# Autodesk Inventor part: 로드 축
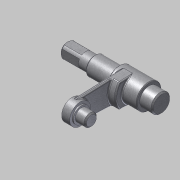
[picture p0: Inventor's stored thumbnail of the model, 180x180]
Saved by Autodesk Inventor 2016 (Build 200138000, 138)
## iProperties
Created: 2015-10
Part Number: 로드 축
Document SubType Name: Modeling
Designer: mdu
Density: 7.86 g/cm^3
Material: 강철, 연강
Mass: 151.797 g
Surface Area: 62.904 cm^2
Volume: 19.3125 cm^3
Appearance: 금속-강(스테인리스, 브러시됨)
Author: mdu
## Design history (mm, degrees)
sketch "스케치1"
  geometry: L1 (-3.325, 13.5)-(-3.325, -13.5) reference; L2 (48.675, -15.7)-(48.675, 15.7) reference; L3 (48.675, 0)-(-26.325, 0); L4 (39.675, -18.06)-(39.675, 18.06) reference; L5 (15.675, 18.855)-(15.675, -18.855) reference; L6 (6.675, 15.7)-(6.675, -15.7) reference; L7 (3.675, -10)-(3.675, 10) reference; L8 (49.675, 7.5)-(39.675, 7.5); L9 (39.675, 7.5)-(39.675, 10); L10 (39.675, 10)-(15.675, 10); L11 (15.675, 10)-(15.675, 7.5); L12 (15.675, 7.5)-(-4.325, 7.5); L13 (-4.325, 7.5)-(-4.325, 6); L14 (-4.325, 6)-(-26.325, 6); L15 (-26.325, 6)-(-26.325, 0); L16 (48.675, 0)-(49.675, 0); L17 (49.675, 0)-(49.675, 7.5); 1 further point
  constraints: 22 end point, 7 perpendicular, 4 point on line, 2 parallel, 1 collinear, 1 midpoint
  dimensions: "d0" = 15 diameter of L8 L3; "d1" = 20 diameter of L10 L3; "d2" = 12 diameter of L14 L3; "d3" = 20 distance of L11.end L12.end; "d4" = 1 distance between parallel lines of L17 L2; "d5" = 75 distance of L3.start L3.end
revolve "회전1" sketch "스케치1" stored, may be unused: angle "d6" = 90 deg
chamfer "모따기1" distance "d7" = 1; stored, may be unused: second distance "d8" = 2, angle "d9" = 45 deg
node "작업 평면1"
sketch "스케치2"
  geometry: 1 further point
sketch "스케치3"
  geometry: L1 (9.993, -0.375)-(8.494, -40.319); L2 (-8.494, -40.319)-(-9.993, -0.375); C1 r 10 at (0, 0) reference; A1 r 8.5 centre (0, -40) between (8.494, -40.319) and (-8.494, -40.319); A2 r 10 centre (0, 0) between (-9.993, -0.375) and (9.993, -0.375) reference; 1 further point
  constraints: 4 end point, 4 point on circle, 4 tangent, 1 centre point, 1 vertical alignment
  dimensions: "d12" = 17 diameter of A1; "d22" = 40 distance of A1.centre A2.centre
  node "투영된 루프1"
extrude "돌출1" join sketch "스케치3" distance "d13" = 6.5; taper "d14" = 0 deg
node "작업 평면3"
  node "작업 평면2"
extrude "돌출2" join sketch "스케치3" stored distance "d17" = 6; taper "d18" = 0 deg
sketch "스케치7"
  geometry: L1 (-9.993, -0.375)-(-8.494, -40.319) reference; L2 (8.494, -40.319)-(9.993, -0.375) reference; A1 r 10 centre (0, 0) between (-9.993, -0.375) and (9.993, -0.375) reference; A2 r 15 centre (0, 0) between (-9.574, -11.547) and (9.574, -11.547); 1 further point
  constraints: 2 point on circle, 2 point on line, 1 centre point, 1 coincident
  dimensions: "d32" = 30 diameter of A2
extrude "돌출6" join sketch "스케치7" distance "d33" = 6; taper "d34" = 0 deg
sketch "스케치5"
  geometry: C1 r 5 at (0, 0) reference; C2 r 6.5 at (0, 0); 1 further point
  constraints: 1 centre point, 1 coincident
  dimensions: "d23" = 13 diameter of C2
  node "참조8"
extrude "돌출4" join sketch "스케치5" distance "d24" = 9; taper "d25" = 0 deg
extrude "돌출5" join sketch "스케치5" distance "d26" = 1; taper "d27" = 0 deg
fillet "모깎기1" dims "d28" = 1
chamfer "모따기2" distance "d29" = 1; stored, may be unused: second distance "d30" = 2, angle "d31" = 45 deg
chamfer "모따기3" distance "d35" = 0.5; stored, may be unused: second distance "d36" = 2, angle "d37" = 45 deg
sketch "스케치8"
  geometry: L1 (-3.25, 5.044)-(3.25, 5.044); L2 (5.044, 3.25)-(5.044, -3.25); L3 (3.25, -5.044)-(-3.25, -5.044); L4 (-5.044, -3.25)-(-5.044, 3.25); 2 further points
  constraints: 8 end point, 6 perpendicular, 1 horizontal, 9 other
  dimensions: "d38" = 6.5 distance of L3.start L3.end
extrude "돌출7" cut sketch "스케치8" distance "d39" = 15; taper "d40" = 0 deg
node "솔리드1"
node "참조1"
node "참조2"
node "참조3"
node "참조4"
node "참조5"
node "참조6"
other parameters: "d10" = -8.5, "d15" = -1, "d16" = -3
